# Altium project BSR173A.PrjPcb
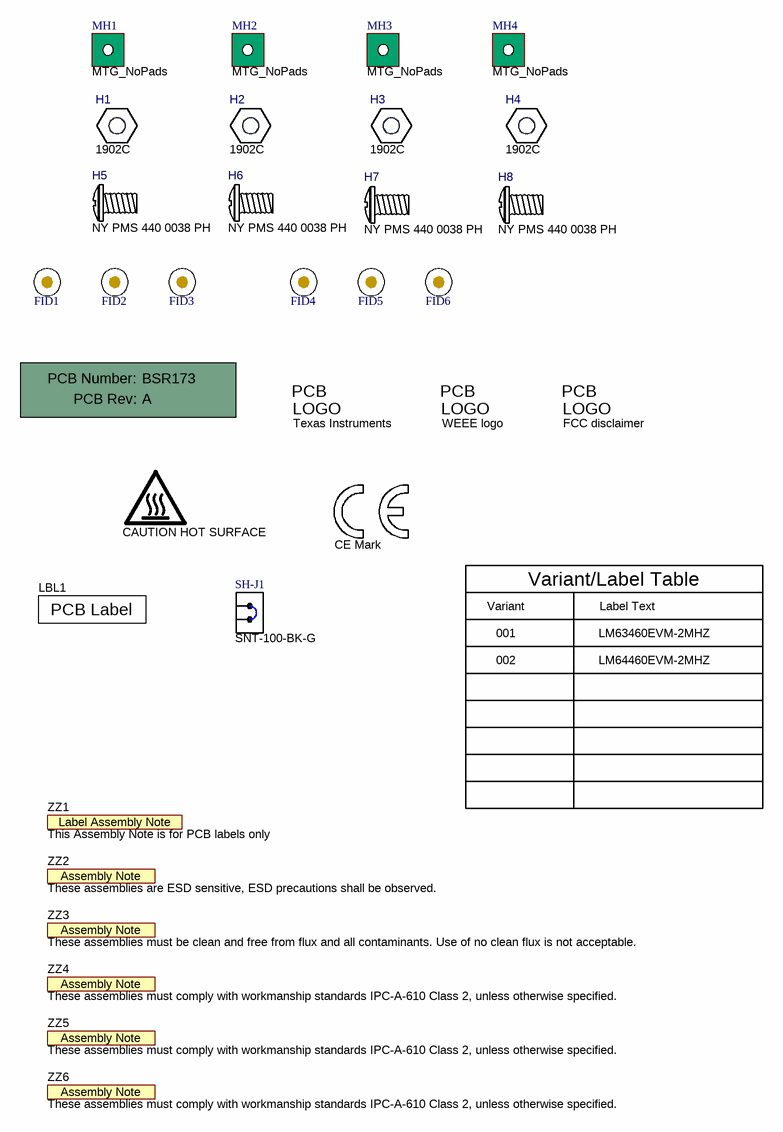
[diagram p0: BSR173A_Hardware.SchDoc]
CopyrightYear: 2020; PCB_Layout: T. Jacobs; PCB_Rev: A; PRJ_Customer: Public Release; PRJ_Engineer: Tim Hagarty; PRJ_Number: BSR173; PRJ_Title: LM64460EVM-2MHz; SCH_Rev: A; TechSupport: http://www.ti.com/support; TID: N/A
2 sheets, 73 parts. Net scope: global (net labels, ports and power ports of the same name join across sheets).
Board file: BSR173A.PcbDoc
Sheets:
  BSR173A_Hardware.SchDoc
  BSR173A.SchDoc

## Sheet BSR173A_Hardware.SchDoc: LM64460 HARDWARE
size 431 x 279 mm; Date: Not shown in title block; ApprovedBy: Not shown in title block; CheckedBy: Not shown in title block; Author: Not shown in title block; CompanyName: Not shown in title block; DrawnBy: T JACOBS; Engineer: Not shown in title block; Organization: Not shown in title block; Address1: Not shown in title block; Address2: Not shown in title block; Address3: Not shown in title block; Address4: Not shown in title block; DocumentNumber: 1; Revision: Use project parameter SCH_Rev; SheetNumber: 1; SheetTotal: 2; PageSetup: Record=PageOptions¦CenterHorizontal=True¦CenterVertical=True¦PrintScale=1.00¦XCorrection=1.00¦YCorrection=1.00¦PrintKind=0¦BorderSize=5000000¦LeftOffset=0¦BottomOffset=0¦Orientation=2¦PaperLength=1000¦PaperWidth=1000¦Scale=100¦PaperSource=15¦PrintQuality=600¦MediaType=1¦DitherType=10¦PaperKind=Letter¦PrintScaleMode=1

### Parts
!PCB1  Printed Circuit Board  (value not drawn)  (mechanical)
FID1  Fiducial  [Fiducial10-20]  (value not drawn)
FID2  Fiducial  [Fiducial10-20]  (value not drawn)
FID3  Fiducial  [Fiducial10-20]  (value not drawn)
FID4  Fiducial  [Fiducial10-20]  (value not drawn)
FID5  Fiducial  [Fiducial10-20]  (value not drawn)
FID6  Fiducial  [Fiducial10-20]  (value not drawn)
H1  1902C  [Keystone_1902C]  (mechanical)
H2  1902C  [Keystone_1902C]  (mechanical)
H3  1902C  [Keystone_1902C]  (mechanical)
H4  1902C  [Keystone_1902C]  (mechanical)
H5  NY PMS 440 0038 PH  (mechanical)
H6  NY PMS 440 0038 PH  (mechanical)
H7  NY PMS 440 0038 PH  (mechanical)
H8  NY PMS 440 0038 PH  (mechanical)
LBL1  THT-14-423-10  [Label_650x200]  (value not drawn)
Logo1  Texas Instruments  [TI_Stacked_Overlay_Small]  (no BOM)
Logo2  WEEE logo  [WEEE_Minimum]  (no BOM)
Logo3  FCC disclaimer  [FCC_disclaimer]  (no BOM)
LOGO4  CAUTION HOT SURFACE  [IEC_HotSurface_Small]  (no BOM)
LOGO5  CE Mark  [CE_Mark_5mm]  (no BOM)
MH1  MTG_NoPads  [MTG_159mil]  (no BOM)
MH2  MTG_NoPads  [MTG_159mil]  (no BOM)
MH3  MTG_NoPads  [MTG_159mil]  (no BOM)
MH4  MTG_NoPads  [MTG_159mil]  (no BOM)
SH-J1  SNT-100-BK-G  [SNT-100-BK-G]
ZZ1  This Assembly Note is for PCB labels only  [AssemblyNoteLabel]  (no BOM)
ZZ2  These assemblies are ESD sensitive, ESD precautions shall be observed.  [AssemblyNote]  (no BOM)
ZZ3  These assemblies must be clean and free from flux and all contaminants. Use of no clean flux is not acceptable.  [AssemblyNote]  (no BOM)
ZZ4  These assemblies must comply with workmanship standards IPC-A-610 Class 2, unless otherwise specified.  [AssemblyNote]  (no BOM)
ZZ5  These assemblies must comply with workmanship standards IPC-A-610 Class 2, unless otherwise specified.  [AssemblyNote]  (no BOM)
ZZ6  These assemblies must comply with workmanship standards IPC-A-610 Class 2, unless otherwise specified.  [AssemblyNote]  (no BOM)

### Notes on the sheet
- Variant
- 001
- Variant/Label Table
- Label Text
- LM63460EVM-2MHZ
- 002
- LM64460EVM-2MHZ

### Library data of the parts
!PCB1 = CMP-0003618-2: Manufacturer: Any; PartNumber: BSR173
FID1-FID6 = CMP-0077181-1: Fiducial mark.  There is nothing to buy or mount.
H1-H4 = CMP-0003610-1: Standoff, Hex, 0.5"L #4-40 Nylon; Manufacturer: Keystone; CompType: Hardware
H5-H8 = CMP-0003667-1: Screw, Pan Head , 4-40, 3/8", Nylon; Manufacturer: B&F Fastener Supply; CompType: Hardware
LBL1 = CMP-0003625-1: Thermal Transfer Printable Labels, 0.650" W x 0.200" H - 10,000 per roll; Manufacturer: Brady; Note: Size: 0.65" x 0.20 "
Logo1 = CMP-0074838-1: Texas Instrument Corporate Signature; SymbolCreator: a0412235; Lib Reference: TI_Logo
Logo2 = CMP-0074769-1
Logo3 = CMP-0074847-1: FCC_disclaimer
LOGO4 = CMP-0074837-2: IEC 61010-1 Hot Surface Warning; Manufacturer: Texas Instruments; SymbolCreator: a0412235; CompType: IC; AEC Category: Q200
LOGO5 = CMP-0074844-1: SymbolCreator: a0412235
MH1-MH4 = CMP-0078424-2: PCB Mounting Hole, No Pad; Manufacturer: Any; Key: Mounting Hole (non-standard) No Pad
SH-J1 = CMP-0003623-3: Shunt, 100mil, Gold plated, Black; Alternate PartNumber: 969102-0000-DA; Manufacturer: Samtec; Alternate Manufacturer: 3M; Value: 1x2; Note: You can "mate" this to a header by matching the designator.  i.e. use SH-J3 for header J3
ZZ1 = CMP-0003616-3
ZZ2 = CMP-0077236-1
ZZ3 = CMP-0077237-1
ZZ4-ZZ6 = CMP-0077238-1

## Sheet BSR173A.SchDoc: LM64460 BUCK REGULATOR
size 431 x 279 mm; Date: Not shown in title block; ApprovedBy: Not shown in title block; CheckedBy: Not shown in title block; Author: Not shown in title block; CompanyName: Not shown in title block; DrawnBy: T Jacobs; Engineer: Not shown in title block; Organization: Not shown in title block; Address1: Not shown in title block; Address2: Not shown in title block; Address3: Not shown in title block; Address4: Not shown in title block; DocumentNumber: 2; Revision: Use project parameter SCH_Rev; SheetNumber: 2; SheetTotal: 2; PageSetup: Record=PageOptions¦CenterHorizontal=True¦CenterVertical=True¦PrintScale=1.00¦XCorrection=1.00¦YCorrection=1.00¦PrintKind=0¦BorderSize=5000000¦LeftOffset=0¦BottomOffset=0¦Orientation=2¦PaperLength=1000¦PaperWidth=1000¦Scale=100¦PaperSource=15¦PrintQuality=600¦MediaType=1¦DitherType=10¦PaperKind=Letter¦PrintScaleMode=1
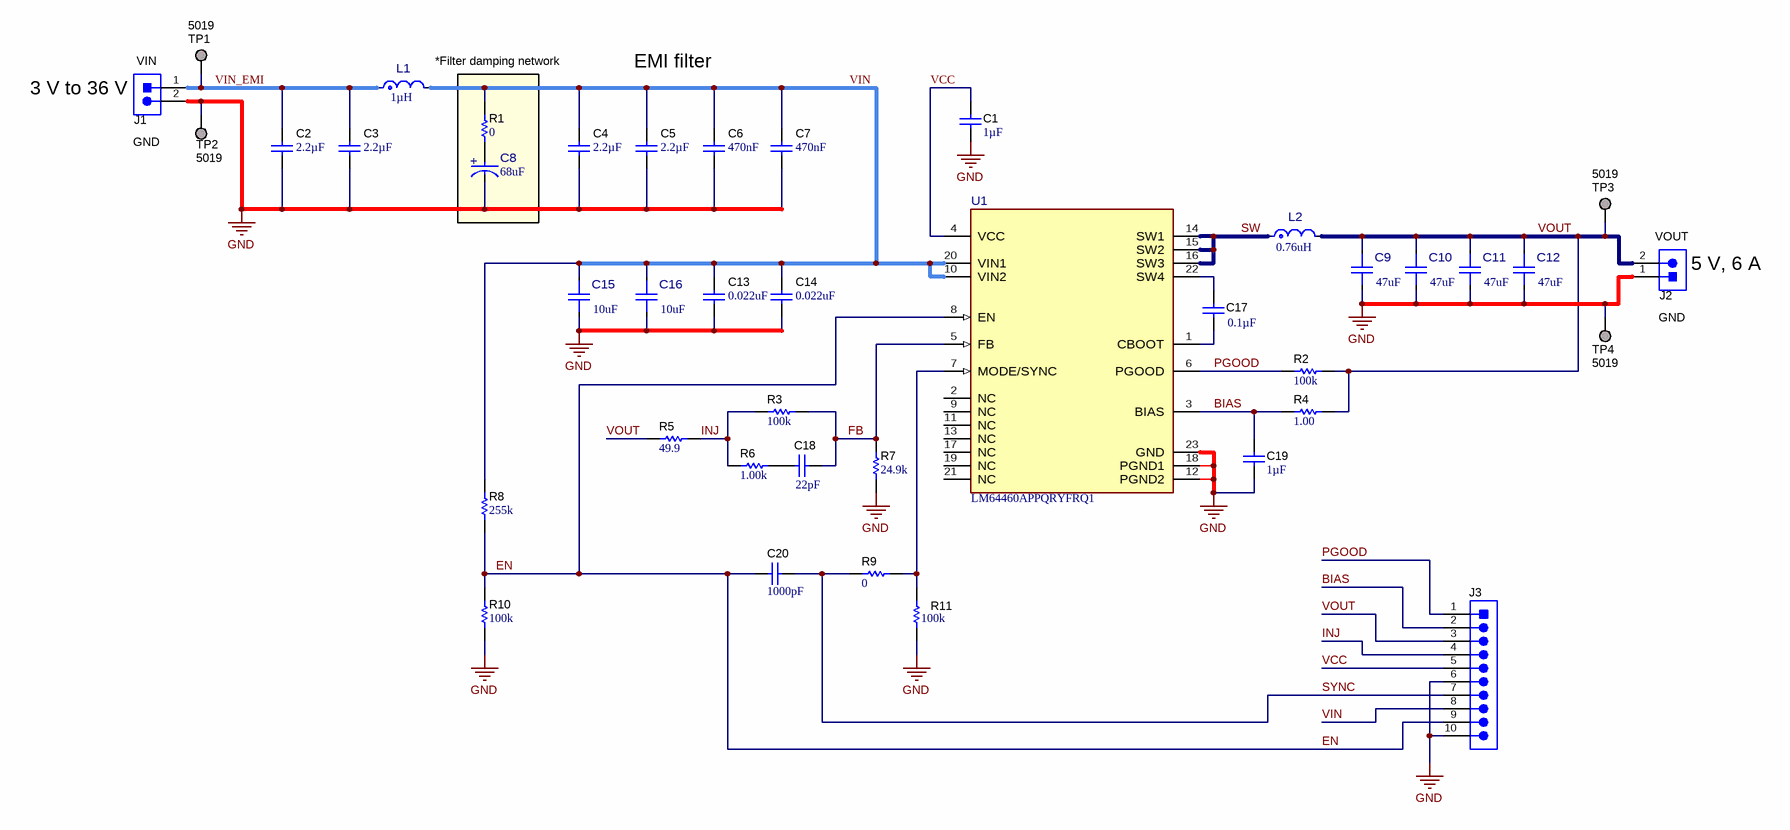
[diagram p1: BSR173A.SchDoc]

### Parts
C1  Cap_F: 1µF  [0603L]  (hidden comment: C0603C105K4RACAUTO)
C2  Cap_F: 2.2µF  [0805L]  (hidden comment: CGA4J3X7R1H225K125AB)
C3  Cap_F: 2.2µF  [0805L]  (hidden comment: CGA4J3X7R1H225K125AB)
C4  Cap_F: 2.2µF  [0805L]  (hidden comment: CGA4J3X7R1H225K125AB)
C5  Cap_F: 2.2µF  [0805L]  (hidden comment: CGA4J3X7R1H225K125AB)
C6  Cap_F: 470nF  [0603L]  (hidden comment: CGA3E3X7R1H474K080AE)
C7  Cap_F: 470nF  [0603L]  (hidden comment: CGA3E3X7R1H474K080AE)
C8  ValueDisplayed: 68uF  [FP-EEE-FN1H680XL_RADIAL-MFG]  (hidden comment: EEE-FN1H680XL)
C9  ValueDisplayed: 47uF  [FP-CGA6P1X7S1A476M250AC_1210-MFG]  (hidden comment: CGA6P1X7S1A476M250AC)
C10  ValueDisplayed: 47uF  [FP-CGA6P1X7S1A476M250AC_1210-MFG]  (hidden comment: CGA6P1X7S1A476M250AC)
C11  ValueDisplayed: 47uF  [FP-CGA6P1X7S1A476M250AC_1210-MFG]  (hidden comment: CGA6P1X7S1A476M250AC)
C12  ValueDisplayed: 47uF  [FP-CGA6P1X7S1A476M250AC_1210-MFG]  (hidden comment: CGA6P1X7S1A476M250AC)
C13  ValueDisplayed: 0.022uF  [0402L]  (hidden comment: GRM155R71H223KA12D)
C14  ValueDisplayed: 0.022uF  [0402L]  (hidden comment: GRM155R71H223KA12D)
C15  ValueDisplayed: 10uF  [FP-CNA6P1X7R1H106K250AE_1210-MFG]  (hidden comment: CNA6P1X7R1H106K250AE)
C16  ValueDisplayed: 10uF  [FP-CNA6P1X7R1H106K250AE_1210-MFG]  (hidden comment: CNA6P1X7R1H106K250AE)
C17  ValueDisplayed: 0.1µF  [0402L]  (hidden comment: C0402C104K8RACTU)
C18  ValueDisplayed: 22pF  [0402L]  (hidden comment: CGA2B2NP01H220J050BA)
C19  Cap_F: 1µF  [0603L]  (hidden comment: C0603C105K4RACAUTO)
C20  ValueDisplayed: 1000pF  [0402L]  (hidden comment: CGA2B2X7R1H102K050BA)
J1  1729018  [Phoenix_1729018]  (value not drawn)
J2  1729018  [Phoenix_1729018]  (value not drawn)
J3  TSW-110-07-G-S  [TSW-110-07-G-S]  (value not drawn)
L1  Ind_H: 1µH  [FP-XGL4020-102MEC_SMT_IND_4MM0_4MM0-MFG]  (hidden comment: XGL4020-102MEC)
L2  value 0.76uH  [FP-XGL4030-761MEC_SMD_IND_4MM0_4MM0-MFG]  (hidden comment: XGL4030-761MEC)
R1  ValueDisplayed: 0  [0603L]  (hidden comment: CRCW06030000Z0EA)
R2  ValueDisplayed: 100k  [0402L]  (hidden comment: CRCW0402100KFKED)
R3  ValueDisplayed: 100k  [0402L]  (hidden comment: CRCW0402100KFKED)
R4  ValueDisplayed: 1.00  [0402L]  (hidden comment: CRCW04021R00FKED)
R5  ValueDisplayed: 49.9  [0402L]  (hidden comment: CRCW040249R9FKED)
R6  ValueDisplayed: 1.00k  [0402L]  (hidden comment: CRCW04021K00FKED)
R7  ValueDisplayed: 24.9k  [0402L]  (hidden comment: CRCW040224K9FKED)
R8  ValueDisplayed: 255k  [0402L]  (hidden comment: CRCW0402255KFKED)
R9  ValueDisplayed: 0  [0402L]  (hidden comment: CRCW04020000Z0ED)
R10  ValueDisplayed: 100k  [0402L]  (hidden comment: CRCW0402100KFKED)
R11  ValueDisplayed: 100k  [0402L]  (hidden comment: CRCW0402100KFKED)
TP1  5019  [Keystone_5019]
TP2  5019  [Keystone_5019]
TP3  5019  [Keystone_5019]
TP4  5019  [Keystone_5019]
U1  LM64460APPQRYFRQ1  [RYF0022A-MFG]

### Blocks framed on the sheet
*Filter damping network: C8 R1

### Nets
GND: C1.2 C2.2 C3.2 C4.2 C5.2 C6.2 C7.2 C8.1(CATHODE) C9.2 C10.2 C11.2 C12.2 C13.2 C14.2 C15.2 C16.2 C19.1 J1.2 J2.1 J3.6 J3.10 R7.2 R10.2 R11.2 TP2.1 TP4.1 U1.12(PGND2) U1.18(PGND1) U1.23(GND)
BIAS: C19.2 J3.2 R4.2 U1.3(BIAS)
EN: C20.2 J3.9 R8.1 R10.1 U1.8(EN)
FB: C18.1 R3.1 R7.1 U1.5(FB)
INJ: J3.4 R3.2 R5.2 R6.1
PGOOD: J3.1 R2.1 U1.6(PGOOD)
SW: L2.1 U1.14(SW1) U1.15(SW2) U1.16(SW3)
SYNC: C20.1 J3.7 R9.2
VCC: C1.1 J3.5 U1.4(VCC)
VIN: C4.1 C5.1 C6.1 C7.1 C13.1 C14.1 C15.1 C16.1 J3.8 L1.2 R1.2 R8.2 U1.10(VIN2) U1.20(VIN1)
VIN_EMI: C2.1 C3.1 J1.1 L1.1 TP1.1
VOUT: C9.1 C10.1 C11.1 C12.1 J2.2 J3.3 L2.2 R2.2 R4.1 R5.1 TP3.1
NetC8_2: C8.2(ANODE) R1.1
NetC17_1: C17.1 U1.22(SW4)
NetC17_2: C17.2 U1.1(CBOOT)
NetC18_2: C18.2 R6.2
NetR9_1: R9.1 R11.1 U1.7(MODE/SYNC)

Not connected (* = marked no-connect by the designer): U1 2(NC) 9(NC) 11(NC) 13(NC) 17(NC) 19(NC) 21(NC)

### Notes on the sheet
- (near J1) VIN
- EMI filter
- (near J1) 3 V to 36 V
- GND
- (near J2) VOUT
- (near J2) 5 V, 6 A
- (near J2) GND

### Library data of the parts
C1 C19 = CMP-0084111-1: CAP, CERM, 1 µF, 16 V,+/- 10%, X7R, AEC-Q200 Grade 1, 0603; Manufacturer: Kemet; SizeAreaWB_mm2: 4.68; SizeArea_mm2: 1.28; AEC Qualified: Y; AEC Category: Q200; Value: 1uF; TaMax_C: 125°C; SizeZ_mm: 1; Polarized: N; TaMin_C: -55°C; VDC_V: 16V; SizeY_mm: 0.8; U/M: EA; SizeX_mm: 1.6; Cap_Case: 0603
C2-C5 = CMP-0007977-2: CAP, CERM, 2.2 uF, 50 V, +/- 10%, X7R, AEC-Q200 Grade 1, 0805; Manufacturer: TDK; TaMin_C: -55°C; ESR_ohm: 3.288m; Polarized: N; SizeAreaWB_mm2: 6.75; Value1: 0.003288 ohm; U/M: EA; Value: 2.2uF; TaMax_C: 125°C; SizeZ_mm: 1.45; SizeX_mm: 2; SizeY_mm: 1.25; Cap_Case: 0805; Value2: 50V; SizeArea_mm2: 2.5; AEC Qualified: Y; IRMS_A: 3.6003A; AEC Grade: 1; AEC Category: Q200
C6 C7 = CMP-0007097-4: CAP, CERM, 0.47 uF, 50 V, +/- 10%, X7R, AEC-Q200 Grade 1, 0603; Manufacturer: TDK; TaMin_C: -55°C; Polarized: N; SizeAreaWB_mm2: 4.68; Value1: Unknown; U/M: EA; Value: 0.47uF; TaMax_C: 125°C; SizeZ_mm: 1; SizeX_mm: 1.6; SizeY_mm: 0.8; Cap_Case: 0603; Value2: 50V; SizeArea_mm2: 1.28; AEC Qualified: Y; AEC Category: Q200
C8 = CMP-0092865-1: 68µF 50V Aluminum Electrolytic Capacitors Radial, Can - SMD 680mOhm @ 100kHz 2000 Hrs @ 105°C; Manufacturer: Panasonic; Esr: 0.68; AEC Qualified: Yes; SizeZ_mm: 8mm; IRMS_A: 195mA; Tolerance_%: 20%; AEC Grade: Grade 2; Dissipation Factor: 10%; Life: 2000Hours; Leakage Current: 34uA
C9-C12 = CMP-0092443-1: Multilayer Ceramic Capacitor 47uF 20% 10V 1210 T/R; Manufacturer: TDK; AEC Grade: Grade 1; TempCo: 22%; Value: 47µF; AEC Qualified: Yes; Temperature Characteristic: X7S; SizeZ_mm: 2.8mm
C13 C14 = CMP-0006684-2: CAP, CERM, 0.022 uF, 50 V, +/- 10%, X7R, 0402; Manufacturer: MuRata; TaMin_C: -55°C; Polarized: N; SizeAreaWB_mm2: 3; Value1: Unknown; U/M: EA; TaMax_C: 125°C; SizeZ_mm: 0.6; SizeX_mm: 1; SizeY_mm: 0.5; Cap_Case: 0402; Value2: 50V; Cap_F: 22nF; AEC Category: Q200
C15 C16 = CMP-0092450-1: 10uF @ ±10% 50V Ceramic Capacitor X7R 1210 (3225 Metric); Manufacturer: TDK; SizeZ_mm: 2.7mm; Value: 10µF; AEC Grade: Grade 1; AEC Qualified: Yes; TempCo: 15%
C17 = CMP-0078241-1: CAP, CERM, 0.1 µF, 10 V,+/- 10%, X7R, 0402; Manufacturer: Kemet; TaMin_C: -55°C; Polarized: N; SizeAreaWB_mm2: 3; U/M: EA; Value: 0.1uF; TaMax_C: 125°C; SizeZ_mm: 0.6; SizeX_mm: 1; SizeY_mm: 0.5; Cap_Case: 0402; Value2: 10V; Cap_F: 100nF; AEC Category: Q200
C18 = CMP-0006311-2: CAP, CERM, 22 pF, 50 V, +/- 5%, C0G/NP0, AEC-Q200 Grade 1, 0402; Manufacturer: TDK; TaMin_C: -55°C; Polarized: N; SizeAreaWB_mm2: 3; Value1: Unknown; U/M: EA; Value: 22pF; TaMax_C: 125°C; SizeZ_mm: 0.6; SizeX_mm: 1; SizeY_mm: 0.5; Cap_Case: 0402; Value2: 50V; AEC Qualified: Y; AEC Category: Q200
C20 = CMP-0006314-2: CAP, CERM, 1000 pF, 50 V, +/- 10%, X7R, AEC-Q200 Grade 1, 0402; Manufacturer: TDK; TaMin_C: -55°C; ESR_ohm: 2.2556; Polarized: N; SizeAreaWB_mm2: 3; Value1: 2.25564 ohm; U/M: EA; Value: 1000pF; TaMax_C: 125°C; SizeZ_mm: 0.6; SizeX_mm: 1; SizeY_mm: 0.5; Cap_Case: 0402; Value2: 50V; AEC Qualified: Y; Cap_F: 1nF; IRMS_A: 280.466mA; AEC Category: Q200
J1 J2 = CMP-0055486-1: TERM BLOCK 2POS 5mm, TH; Manufacturer: Phoenix Contact; CT: TRUE; Green_REACh: Incomplete; CompType: Terminal Block; CNHeader: FALSE; Green_Lifecycle: Not Set
J3 = CMP-0075422-1: Header, 100mil, 10x1, Gold, TH; Manufacturer: Samtec; Pitch_mm: 2.54; Cert_VDE: N; Gender: Male; Cert_CSA: Y; Voltage_V: 550V; Green_REACh: Passed; Current_A: 6.3A; CT: False; Green_Lifecycle: Active; Row_Count: 1; CNHeader: True
L1 = CMP-0086510-2: Shielded Power Inductors; Manufacturer: Coilcraft; Symbol Name: SYM-XGL4020-102MEC; SizeZ_mm: 2.1mm; Isat: 3.8A; DCR_ohm: 9m; Material: Composite; Irms: 12A; AEC Qualified: Yes; AEC Grade: Grade 1
L2 = CMP-0090843-1: Power Inductor, shielded, composite, 0.76uH 20% tol, 5.5mOhms, SFR 72MHz, ISAT 5.6A, IRMS14.2ASMT, RoHS, halogen-free; Manufacturer: Coilcraft; Irms: 14.2A; Shrouded: true; Ind_H: 760nH; TaMin_C: -40°C; AEC Grade: Grade 1; AEC Qualified: Yes; Test Frequency: 1MHz; SizeZ_mm: 3.1mm; TaMax_C: +125°C; DCR_ohm: 5.5m
R1 = CMP-0025697-4: RES, 0, 5%, 0.1 W, AEC-Q200 Grade 0, 0603; Manufacturer: Vishay-Dale; Power_W: 100mW; TempCo: 200 ppm/C; Value_Code: 0000; Value: 0; EIA_Code: E24; SizeX_mm: 1.6; SizeY_mm: 0.8; SizeZ_mm: 1; Value2: 0.1W; SizeArea_mm2: 1.28; AEC Qualified: Y; VDC_V: 75V; AEC Category: Q200
R2 R3 R10 R11 = CMP-0025950-3: RES, 100 k, 1%, 0.063 W, AEC-Q200 Grade 0, 0402; Manufacturer: Vishay-Dale; Power_W: 63mW; TempCo: 100 ppm/C; Value: 100k; EIA_Code: E96; SizeX_mm: 1; SizeY_mm: 0.5; SizeZ_mm: 0.6; Value2: 0.063W; AEC Qualified: Y; VDC_V: 50V; AEC Category: Q200; AEC Grade: 0
R4 = CMP-0026129-2: RES, 1.00, 1%, 0.063 W, AEC-Q200 Grade 0, 0402; Manufacturer: Vishay-Dale; Power_W: 63mW; TempCo: 100 ppm/C; Value_Code: 1R00; Value: 1.00; EIA_Code: E96; Res_ohm: 1; SizeY_mm: 0.5; SizeZ_mm: 0.6; Value2: 0.063W; AEC Qualified: Y; VDC_V: 50V; AEC Category: Q200; AEC Grade: 0
R5 = CMP-0026404-2: RES, 49.9, 1%, 0.063 W, AEC-Q200 Grade 0, 0402; Manufacturer: Vishay-Dale; Power_W: 63mW; TempCo: 100 ppm/C; Value_Code: 49R9; Value: 49.9; EIA_Code: E96; SizeX_mm: 1; SizeY_mm: 0.5; SizeZ_mm: 0.6; Value2: 0.063W; AEC Qualified: Y; VDC_V: 50V; AEC Category: Q200; AEC Grade: 0
R6 = CMP-0026071-3: RES, 1.00 k, 1%, 0.063 W, AEC-Q200 Grade 0, 0402; Manufacturer: Vishay-Dale; Power_W: 63mW; TempCo: 100 ppm/C; Value_Code: 1k00; Value: 1.00k; EIA_Code: E96; Res_ohm: 1k; SizeX_mm: 1; SizeY_mm: 0.5; SizeZ_mm: 0.6; Value2: 0.063W; AEC Qualified: Y; VDC_V: 50V; AEC Category: Q200; AEC Grade: 0
R7 = CMP-0026196-2: RES, 24.9 k, 1%, 0.063 W, AEC-Q200 Grade 0, 0402; Manufacturer: Vishay-Dale; Power_W: 63mW; TempCo: 100 ppm/C; Value_Code: 24k9; Value: 24.9k; EIA_Code: E96; SizeX_mm: 1; SizeY_mm: 0.5; SizeZ_mm: 0.6; Value2: 0.063W; AEC Qualified: Y; VDC_V: 50V; AEC Category: Q200; AEC Grade: 0
R8 = CMP-0026199-2: RES, 255 k, 1%, 0.063 W, AEC-Q200 Grade 0, 0402; Manufacturer: Vishay-Dale; Power_W: 63mW; TempCo: 100 ppm/C; Value: 255k; EIA_Code: E96; SizeX_mm: 1; SizeY_mm: 0.5; SizeZ_mm: 0.6; Value2: 0.063W; AEC Qualified: Y; VDC_V: 50V; AEC Category: Q200; AEC Grade: 0
R9 = CMP-0026822-3: RES, 0, 5%, 0.063 W, AEC-Q200 Grade 0, 0402; Manufacturer: Vishay-Dale; Power_W: 63mW; TempCo: 200 ppm/C; Value_Code: 0000; Value: 0; EIA_Code: E24; SizeX_mm: 1; SizeY_mm: 0.5; SizeZ_mm: 0.6; Value2: 0.063W; AEC Qualified: Y; VDC_V: 50V; AEC Category: Q200
TP1-TP4 = CMP-0055162-1: Test Point, Miniature, SMT; Manufacturer: Keystone; CNHeader: FALSE; Green_Lifecycle: Active; Green_REACh: Passed; CT: TRUE
U1 = CMP-0092919-2: Automotive 3-V to 36-V, 6-A Synchronous Buck DC/DC Converter, Adjustable 1-34.2V, VQFN-FCRLF22; Manufacturer: Texas Instruments; Switching Frequency: 200-2200kHz; Max Duty Cycle: 87%; AEC Qualified: Yes; Output Type: AdjustableProgrammable; Number Of Outputs: 1; TaMax_C: +125°C; Nominal Supply Current: 0.6uA; CompType: IC; SizeZ_mm: 1.05mm; Standoff Height: 0mm; Min Supply Voltage: 3V; TJmax_C: +150°C; AEC Grade: Grade 1; AEC Category: Q200; TaMin_C: -40°C; Max Supply Voltage: 36V

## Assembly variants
001: not fitted C12 C18 R6 R9
002: not fitted C12 C18 C20 R6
